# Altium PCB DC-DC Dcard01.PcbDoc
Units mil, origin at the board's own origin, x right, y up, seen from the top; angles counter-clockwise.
Board outline 1550 x 1330 mil, 2 copper layers (Top Layer, Bottom Layer), stack 62 mil thick; 64 components, 26 nets, 145 pads, 30 vias.
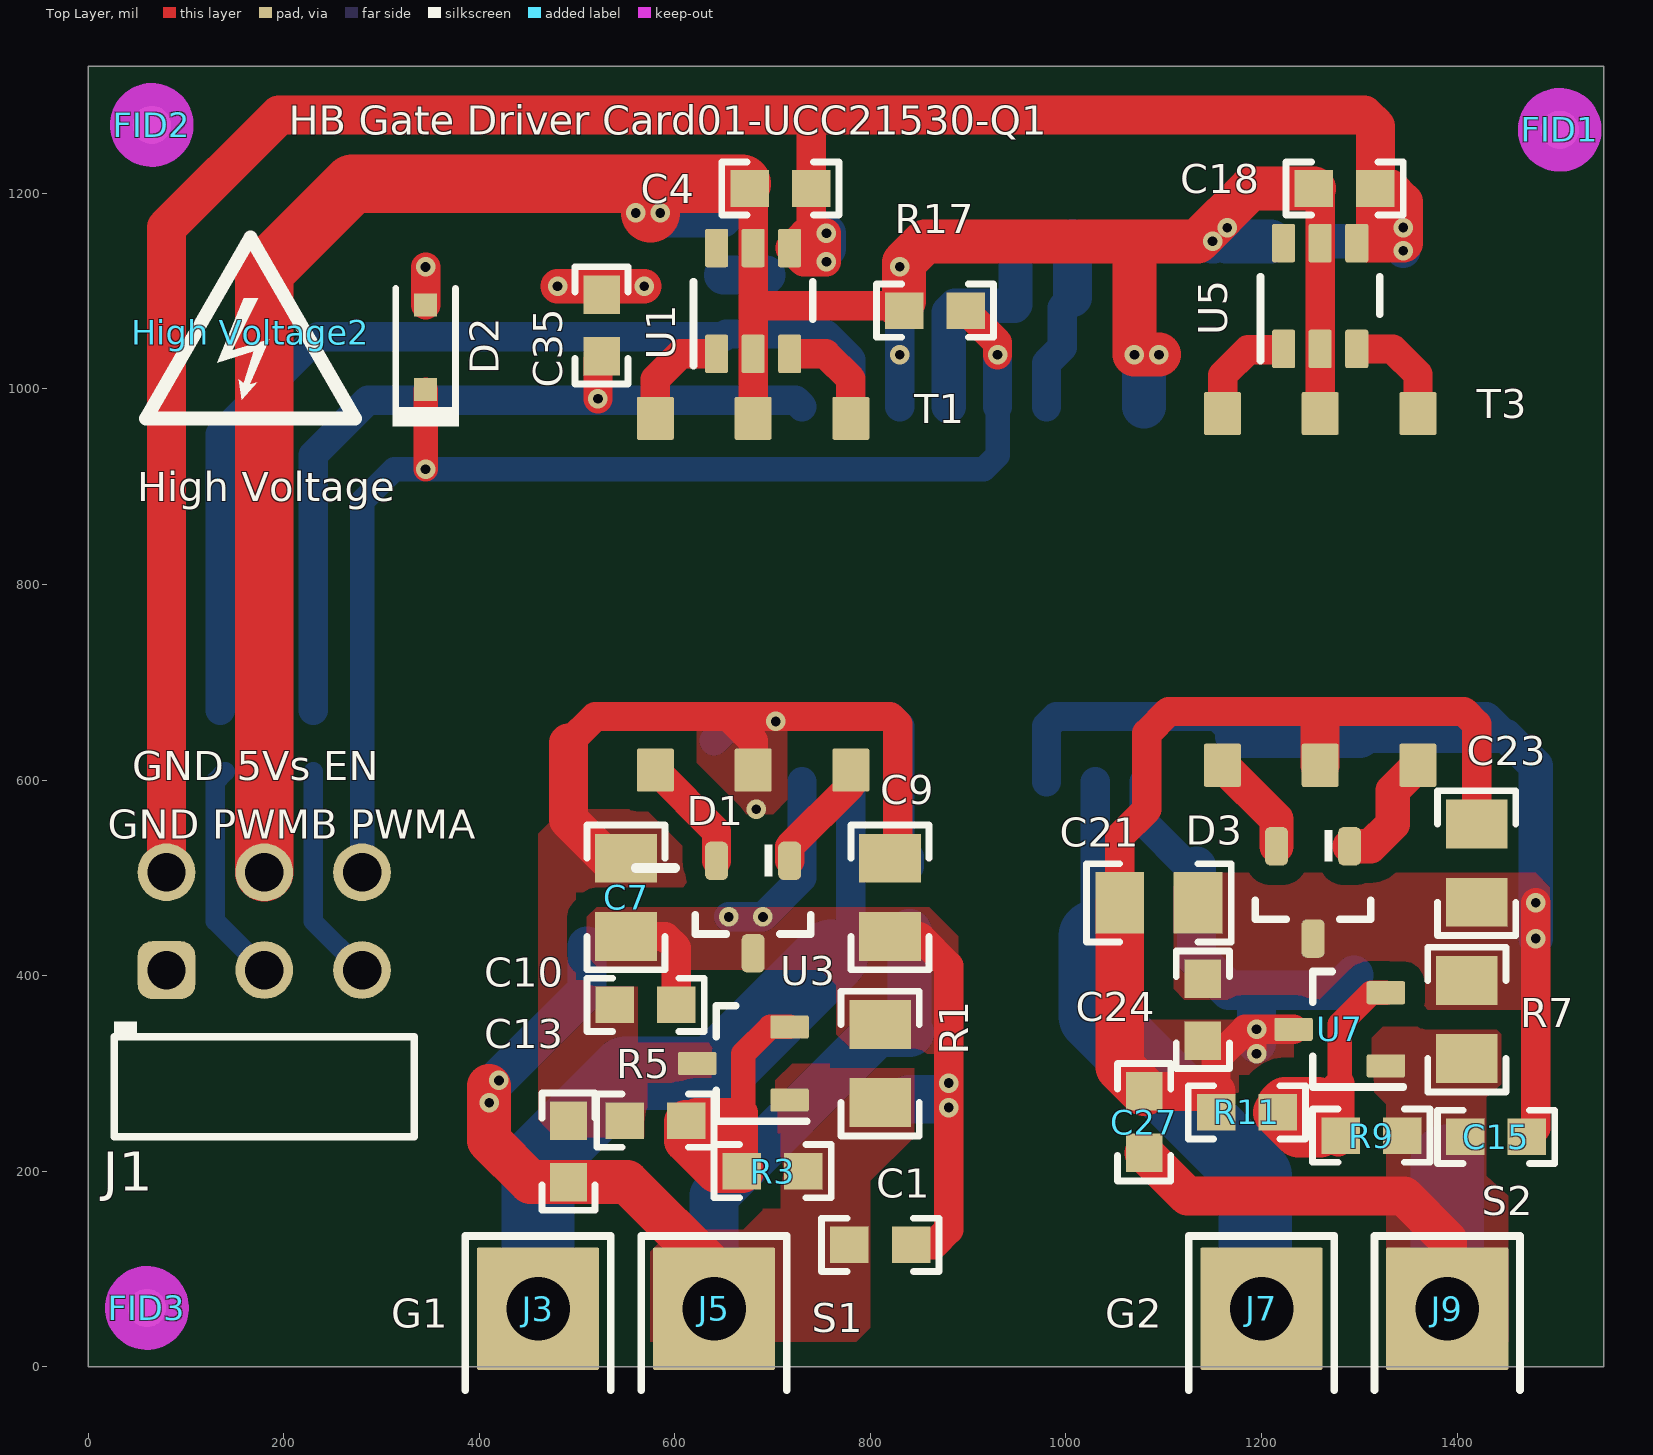
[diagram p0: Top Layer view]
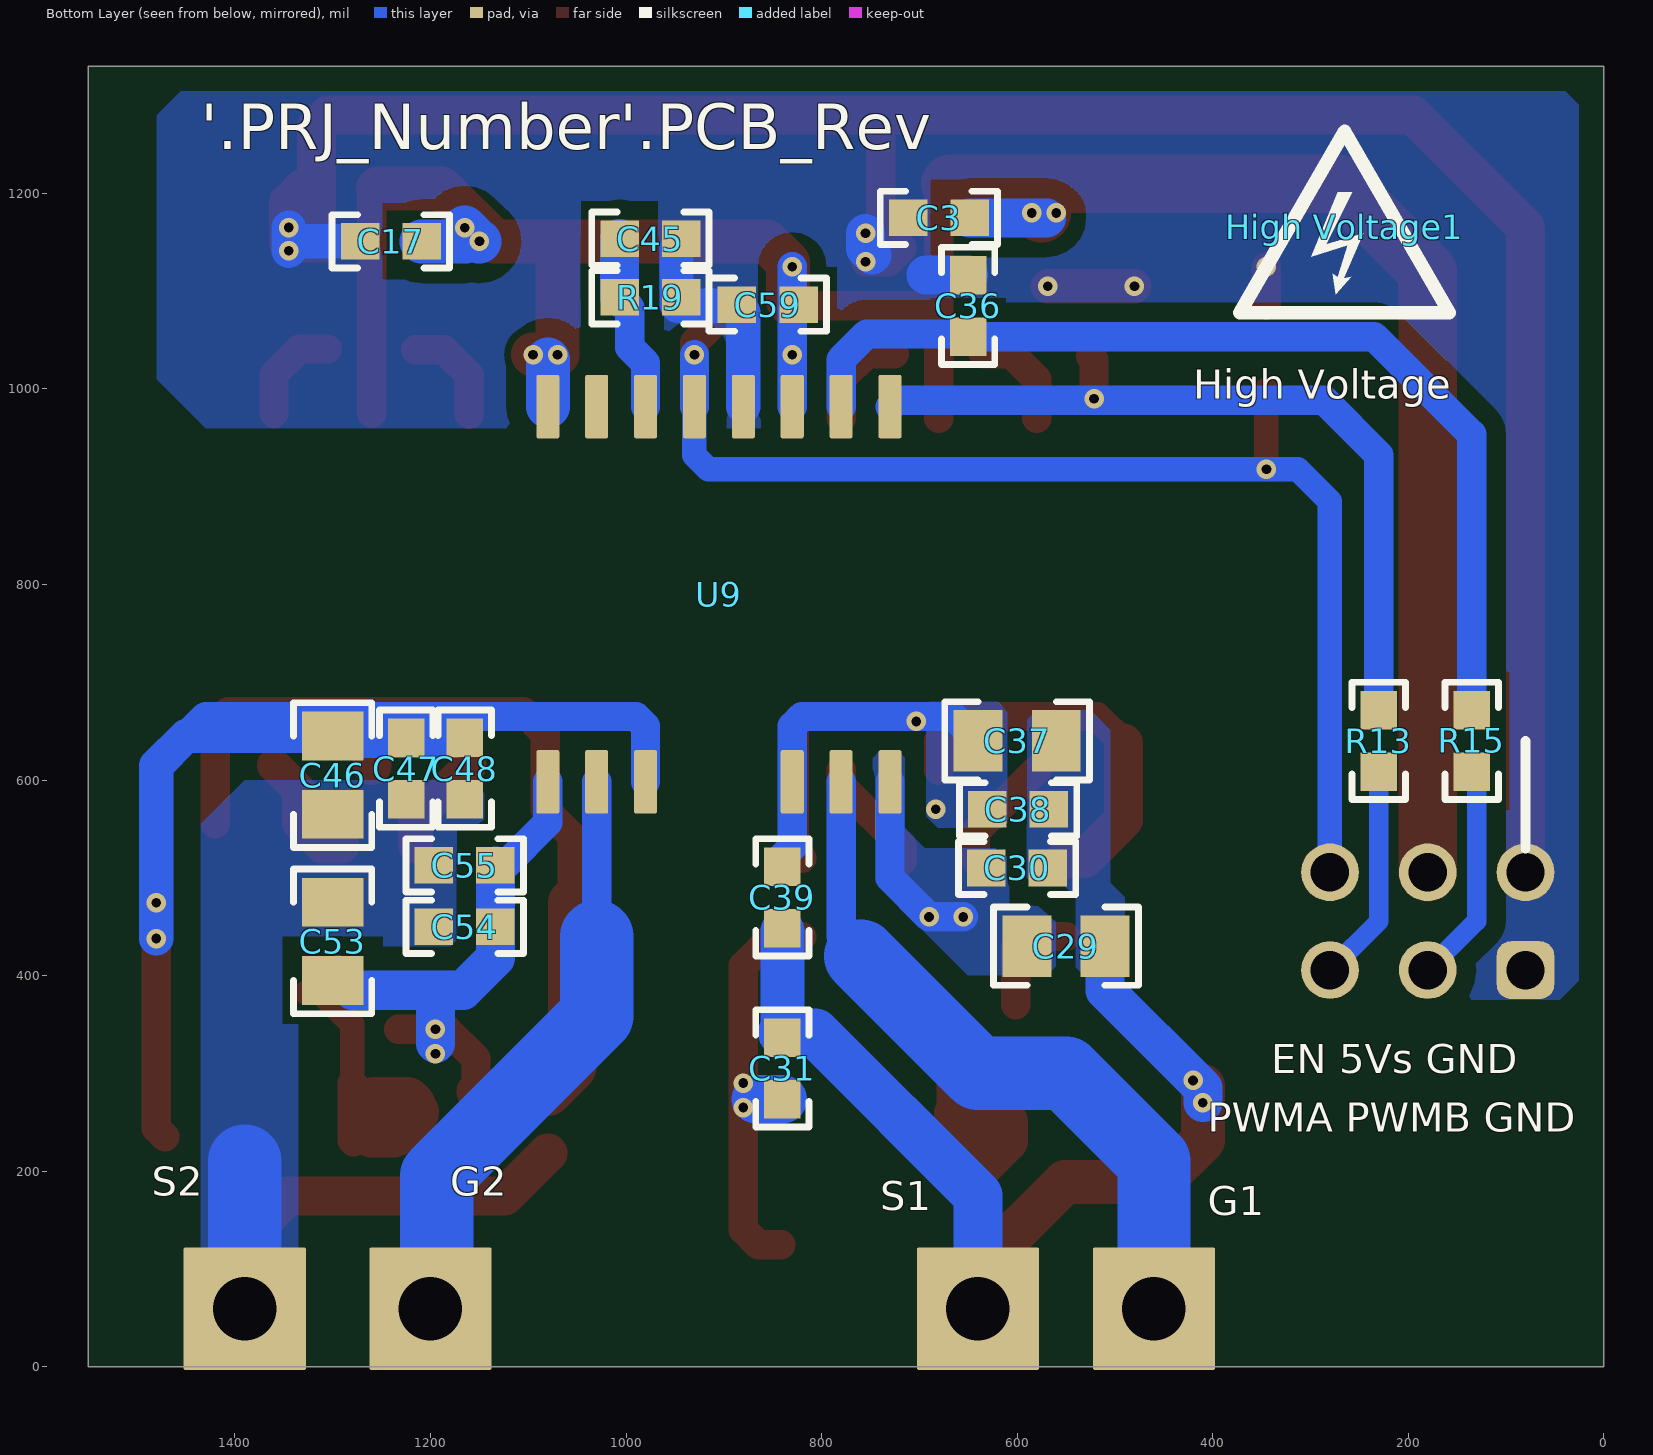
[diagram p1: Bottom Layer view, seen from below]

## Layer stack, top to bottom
Top Solder: solder mask 0.4, Solder Resist, Dk 3.5
Top Layer: signal copper 1.4
Dielectric2: dielectric 59.2, FR-4, Dk 4.8
Bottom Layer: signal copper 1.4
Bottom Solder: solder mask 0.4, Solder Resist, Dk 3.5

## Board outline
0,0 1550,0 1550,1330 0,1330

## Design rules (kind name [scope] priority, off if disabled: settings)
AcuteAngle [All] p1: minimum=4.50000000000000E+0001 checktracksonly=FALSE
AssemblyTestPointUsage [All] p1: valid=2
BoardOutlineClearance BoardOutlineClearance_MountingHoles [OnCopper and InComponentClass('Mounting Holes')] p1: gap=40 ignorepadtopadclearanceinfootprint=FALSE
BoardOutlineClearance BoardOutlineClearance_Poly [OnCopper and IsPoly] p2: gap=25 ignorepadtopadclearanceinfootprint=FALSE
BoardOutlineClearance [OnCopper and Not InComponentClass('Logo') and not InComponentClass('FiducialMark') and not InRegion(1000,500,4000,800) and not InPoly] p3: gap=0 ignorepadtopadclearanceinfootprint=FALSE
Clearance Clearance_Keepouts [((IsTrack Or IsArc) And Not InPoly) And IsFree and IsKeepOut vs ((IsTrack Or IsArc) And Not InPoly) And IsFree and IsKeepOut] p1: gap=0 ignorepadtopadclearanceinfootprint=FALSE
Clearance Clearance_Poly [InPolygon] p2: gap=20 ignorepadtopadclearanceinfootprint=FALSE
Clearance Clearance_FiducialMark [IsKeepOut and InComponentClass('FiducialMark') vs IsPad and InComponentClass('FiducialMark')] p3: gap=0 ignorepadtopadclearanceinfootprint=FALSE
Clearance [All] p4: gap=7.87 ignorepadtopadclearanceinfootprint=FALSE except(0: Arc-Hole Track-Hole SMDPad-Hole THPad-Hole Via-Hole Fill-Hole Poly-Hole Region-Hole Text-Hole)
ComponentClearance ComponentClearance_MountingHoles_FiducialMarks [InComponentClass('Mounting Holes') vs InComponentClass('FiducialMark')] p1: gap=50 collisioncheckmode=3 verticalgap=10 showdistances=FALSE
ComponentClearance ComponentClearance_Shunt [InComponentClass('Header') vs InComponentClass('Shunt')] p2: gap=0 collisioncheckmode=3 verticalgap=0 showdistances=FALSE
ComponentClearance ComponentClearance_Logo [InComponentClass('Logo')] p3: gap=50 collisioncheckmode=3 verticalgap=10 showdistances=FALSE
ComponentClearance ComponentClearance_ScrewToNut [(HasFootprint('NY PMS 440 0025 PH')) vs (HasFootprint('Keystone_1902C'))] p4: gap=5 collisioncheckmode=3 verticalgap=10 showdistances=FALSE
ComponentClearance ComponentClearance_MountingHoles [InComponentClass('Mounting Holes')] p5: gap=250 collisioncheckmode=3 verticalgap=100000 showdistances=FALSE
ComponentClearance ComponentClearance_SmallPassives [HasFootprint('0201*') or HasFootprint('0402*') or HasFootprint('0508') or HasFootprint('0603*') or HasFootprint('0612') or HasFootprint('0805*') or HasFootprint('0815*') or HasFootprint('0830*') or HasFootprint('1206*') or HasFootprint('1210*') or HasFootprint('1808*') or HasFootprint('1812*') or HasFootprint('1825*') or HasFootprint('2010*') or HasFootprint('2220*') or HasFootprint('2225*') or HasFootprint('2512*') or HasFootprint('2728*') or HasFootprint('3518*') vs HasFootprint('0201*') or HasFootprint('0402*') or HasFootprint('0508') or HasFootprint('0603*') or HasFootprint('0612') or HasFootprint('0805*') or HasFootprint('0815*') or HasFootprint('0830*') or HasFootprint('1206*') or HasFootprint('1210*') or HasFootprint('1808*') or HasFootprint('1812*') or HasFootprint('1825*') or HasFootprint('2010*') or HasFootprint('2220*') or HasFootprint('2225*') or HasFootprint('2512*') or HasFootprint('2728*') or HasFootprint('3518*')] p6: gap=14.96 collisioncheckmode=3 verticalgap=10 showdistances=FALSE
ComponentClearance ComponentClearance_THtoSMT [IsThruComponent vs IsSMTComponent] p7: gap=40 collisioncheckmode=3 verticalgap=30 showdistances=FALSE
ComponentClearance ComponentClearance_THtoTH [IsThruComponent vs IsThruComponent] p8: gap=30 collisioncheckmode=3 verticalgap=30 showdistances=FALSE
ComponentClearance [All] p9: gap=30 collisioncheckmode=3 verticalgap=10 showdistances=FALSE
DiffPairsRouting [All] p1: maxlimit=100 minlimit=10 mostfreqgap=10 toplayer_minwidth=15 toplayer_maxwidth=15 toplayer_prefwidth=15 bottomlayer_minwidth=15 bottomlayer_maxwidth=15 bottomlayer_prefwidth=15 maxuncoupledlength=1000
FabricationTestPointUsage TestPointUsage [All] p1: valid=2 allowmultiple=FALSE
FabricationTestpoint Testpoint [All] p1: side=3 testpointundercomponent=TRUE minsize=40 maxsize=100 preferedsize=60 minholesize=0 maxholesize=40 preferedholesize=32 testpointgrid=1 allowsidetop=TRUE allowsidebottom=TRUE usegrid=TRUE gridtolerance=0.01
FanoutControl Fanout_LCC [IsLCC] p1: bgadir=Out bgaviamode=Centered fanoutstyle=Auto fanoutdirection=Alternating viagrid=1 // Fanout_LCC (Default Rule)
FanoutControl Fanout_BGA [IsBGA] p2: bgadir=Out bgaviamode=Centered fanoutstyle=Auto fanoutdirection=Alternating viagrid=1 // Fanout_BGA (Default Rule)
FanoutControl Fanout_Default [All] p4: bgadir=Out bgaviamode=Centered fanoutstyle=Auto fanoutdirection=Alternating viagrid=1 // Fanout_Default (Default Rule)
FanoutControl Fanout_Small [(CompPinCount < 5)] p5: bgadir=Out bgaviamode=Centered fanoutstyle=Auto fanoutdirection=OutThenIn viagrid=1 // Fanout_Small (Default Rule)
HoleSize [All] p1: absolutevalues=TRUE maxlimit=251 minlimit=7.87 maxpercent=80.000 minpercent=20.000
MinimumAnnularRing MinimumAnnularRing_ThermalPadVias [IsVia and InAnyComponent] p1: minimumring=5.91
MinimumAnnularRing [All] p2: minimumring=4
MinimumSolderMaskSliver MinimumSolderMaskSliver_Logo [InComponentClass('Logo') vs InComponentClass('Logo')] p1: minsoldermaskwidth=0.7
MinimumSolderMaskSliver [All] p2: minsoldermaskwidth=0.9
PlaneConnect [All] p1: planeconnectstyle=Relief reliefexpansion=10 reliefentries=4 reliefconductorwidth=10 reliefairgap=10
PolygonConnect [All] p1: connectstyle=Direct reliefconductorwidth=10 reliefentries=4 polygonreliefangle="90 Angle" airgapwidth=10
RoutingVias ThermalPadVias [IsVia and InAnyComponent] p1: holewidth=7.87 width=19.68 viastyle="Through Hole" minholewidth=7.87 minwidth=19.68 maxholewidth=12.99 maxwidth=23.62
RoutingVias [All] p2: holewidth=16 width=34 viastyle="Through Hole" minholewidth=4 minwidth=18 maxholewidth=40 maxwidth=65
SilkToBoardRegionClearance [Not ((IsComment or IsDesignator) And (Hide <> 'False')) and not InRegion(1000,500,4000,800)] p1:
SilkToSilkClearance SilkToSilkClearance_Pb-FreeLogo [(HasFootprint('Pb-Free_Overlay_Medium') OR HasFootprint('Pb-Free_Overlay_Small')) vs (HasFootprint('Pb-Free_Overlay_Medium') OR HasFootprint('Pb-Free_Overlay_Small'))] p1: silktosilkclearance=0
SilkToSilkClearance [All] p2: silktosilkclearance=4
SilkToSolderMaskClearance SilkToComponentPadClearance [(IsPad or IsFill or IsRegion) and InAnycomponent] p1: minsilkscreentomaskgap=0 clearancetoexposedcopper=TRUE
SilkToSolderMaskClearance "Silk to Solder Mask Opening" [All] p2: minsilkscreentomaskgap=0 clearancetoexposedcopper=FALSE
SolderMaskExpansion [All] p1: expansion=1.97
Width [All] p1: maxlimit=150 minlimit=6 preferedwidth=10 checkconnectedcopper=TRUE
15 further rules are at their usual default settings.

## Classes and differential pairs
component class "TIDM-02009_Gate Drive1": C1 C3 C4 C7 C9 C10 C13 C15 C17 C18 C21 C23 C24 C27 C29 C30 C31 C35 C36 C37 C38 C39 C45 C46 C47 C48 C53 C54 C55 C59 D1 D2 D3 J1 J3 J5 J7 J9 R1 R3 R5 R7 R9 R11 R13 R15 R17 R19 T1 T3 U1 U3 U5 U7 U9
component class Header: J1
component class TIDM-02009_DC_Hardware: FID1 FID2 FID3 "High Voltage1" "High Voltage2" ZZ1 ZZ2 ZZ3 ZZ4
component class FiducialMark: FID1 FID2 FID3
component class AssemblyNote: ZZ1 ZZ2 ZZ3 ZZ4

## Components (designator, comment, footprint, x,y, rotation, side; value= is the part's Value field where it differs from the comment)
C1 "CGA3E2X7R1E104K080AA" 0603 810,124.5 r180 top value=0.1uF
C3 "GRT188C81A106ME13D" 0603 680,1175 r0 bottom value=10uF
C4 "CGA3E2X7R1E104K080AA" 0603 707.91,1205 r0 top value=0.1uF
C7 "GRT21BR61H475KE13L" 0805_HV 550,480 r90 top value=4.7uF
C9 "GRT21BR61H475KE13L" 0805_HV 820,480 r90 top value=4.7uF
C10 "CGA3E2X7R1E104K080AA" 0603 570,370 r180 top value=0.1uF
C13 "CGA3E2X7R1E104K080AA" 0603 491.16,220 r90 top value=0.1uF
C15 "CGA3E2X7R1E104K080AA" 0603 1440,235 r180 top value=0.1uF
C17 "GRT188C81A106ME13D" 0603 1240.57,1150.98 r0 bottom value=10uF
C18 "CGA3E2X7R1E104K080AA" 0603 1285,1205 r0 top value=0.1uF
C21 "GRT21BR61H475KE13L" 0805_HV 1095,474.42 r180 top value=4.7uF
C23 "GRT21BR61H475KE13L" 0805_HV 1420,515 r90 top value=4.7uF
C24 "CGA3E2X7R1E104K080AA" 0603 1140,365 r270 top value=0.1uF
C27 "CGA3E2X7R1E104K080AA" 0603 1080,250 r90 top value=0.1uF
C29 "GRT21BR61H475KE13L" 0805_HV 550,430 r180 bottom value=4.7uF
C30 "CGA3E2X7R1E104K080AA" 0603 600,510 r180 bottom value=0.1uF
C31 "CGA3E2C0G1H103J080AA" 0603 840,305 r90 bottom value=0.01uF
C35 "GCM1885C2A101JA16D" 0603 525,1065 r90 top value=100pF
C36 "GCM1885C2A101JA16D" 0603 650,1085 r90 bottom value=100pF
C37 "GRT21BR61H475KE13L" 0805_HV 600,640 r0 bottom value=4.7uF
C38 "CGA3E2X7R1E104K080AA" 0603 598.98,570 r0 bottom value=0.1uF
C39 "CGA3E2C0G1H103J080AA" 0603 840,480 r90 bottom value=0.01uF
C45 "GRM188R71C222KA01D" 0603 975,1153.62 r180 bottom value=2200pF
C46 "GRT21BR61H475KE13L" 0805_HV 1300,605 r270 bottom value=4.7uF
C47 "CGA3E2X7R1E104K080AA" 0603 1225,611.69 r270 bottom value=0.1uF
C48 "CGA3E2C0G1H103J080AA" 0603 1165,611.69 r270 bottom value=0.01uF
C53 "GRT21BR61H475KE13L" 0805_HV 1300,435 r270 bottom value=4.7uF
C54 "CGA3E2X7R1E104K080AA" 0603 1165,449.69 r180 bottom value=0.1uF
C55 "CGA3E2C0G1H103J080AA" 0603 1165,512.68 r180 bottom value=0.01uF
C59 "CGA3E2X7R1E104K080AA" 0603 855,1086.3 r0 bottom value=0.1uF
D1 "BAV70-E3-08" SOT-23 680,470 r270 top value=70V
D2 "SZMM3Z3V3ST1G" SOD-323 345,1042.56 r90 top value=3.3V
D3 "BAV70-E3-08" SOT-23 1252.72,485 r270 top value=70V
FID1 "Fiducial" Fiducial10-20 1505,1265 r0 top
FID2 "Fiducial" Fiducial10-20 65,1270 r0 top
FID3 "Fiducial" Fiducial10-20 60,60 r0 top
"High Voltage1" "DANGER HIGH VOLTAGE" IEC_HighVoltage_Small 265,1165.97 r180 bottom
"High Voltage2" "DANGER HIGH VOLTAGE" IEC_HighVoltage_Small 166,1057.76 r0 top
J1 "90122-0763" Molex_90122-0763 180,455.59 r90 top
J3 "3620-2-32-15-00-00-08-0" Mill-Max_3620-2-32-xx-00-00-08-0 460,-40 r0 top
J5 "3620-2-32-15-00-00-08-0" Mill-Max_3620-2-32-xx-00-00-08-0 640,-40 r0 top
J7 "3620-2-32-15-00-00-08-0" Mill-Max_3620-2-32-xx-00-00-08-0 1200,-40 r0 top
J9 "3620-2-32-15-00-00-08-0" Mill-Max_3620-2-32-xx-00-00-08-0 1390,-40 r0 top
R1 "ERJ-P06F4701V" 0805_HV 810,310 r90 top value=4.70k
R3 "RT0603DRE073K01L" 0603 700,200 r0 top value=3.01k
R5 "RT0603DRE074K99L" 0603 580,251.5 r0 top value=4.99k
R7 "ERJ-P06F4701V" 0805_HV 1410,355 r90 top value=4.70k
R9 "RT0603DRE073K01L" 0603 1312.28,236.3 r0 top value=3.01k
R11 "RT0603DRE074K99L" 0603 1185,260 r0 top value=4.99k
R13 "CRCW06030000Z0EA" 0603 230.1,640 r270 bottom value=0
R15 "CRCW06030000Z0EA" 0603 135,640 r270 bottom value=0
R17 "RC0603JR-075K1L" 0603 866.02,1080 r0 top value=5.1k
R19 "CRCW06033K09FKEA" 0603 975,1093.62 r0 bottom value=3.09k
T1 "750317722" Wurth_750317722 680,790 r270 top
T3 "750317722" Wurth_750317722 1260,795 r270 top
U1 "SN6505DQDBVRQ1" DBV0006A_N 680,1090 r90 top
U3 "TL431AQDBZRQ1" DBZ0003A_N 670,310 r180 top
U5 "SN6505DQDBVRQ1" DBV0006A_N 1260,1095 r90 top
U7 "TL431AQDBZRQ1" DBZ0003A_N 1280,345 r180 top
U9 "UCC21530QDWKRQ1" DWK0014A 905,790 r270 bottom
ZZ1 "This Assembly Note is for PCB labels only" AssemblyNoteLabel 185,3938 r0 top
ZZ2 "These assemblies are ESD sensitive, ESD precautions shall be observed." AssemblyNote 185,3829.11 r0 top
ZZ3 "These assemblies must be clean and free from flux and all contaminants. Use of no clean flux is not acceptable." AssemblyNote 185,3740.56 r0 top
ZZ4 "These assemblies must comply with workmanship standards IPC-A-610 Class 2, unless otherwise specified." AssemblyNote 185,3652 r0 top

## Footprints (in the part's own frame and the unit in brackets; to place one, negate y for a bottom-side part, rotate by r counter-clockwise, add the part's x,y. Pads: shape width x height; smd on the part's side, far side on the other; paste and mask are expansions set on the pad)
0603 [mm] "0603 from SM-752 data"
  rect 1x0.95 smd: 1(-0.8,0) 2(0.8,0)
  silkscreen extent -1.52,-0.69 1.52,0.69, body extent -0.87,-0.47 0.87,0.47, height 1
0805_HV [mil] "0805 with 30mil clearance between pads"
  rect 50x63 smd: 1(-40,0) 2(40,0)
  silkscreen extent -74,-40 74,40, body extent -43,-29 43,29, height 57
AssemblyNote [mil] "Assembly Note"
AssemblyNoteLabel [mil] "Assembly Note for PCB Labels"
DBV0006A_N [mm] "SOT23, 6-Leads, Body 2.9x1.6mm, Pitch 0.95mm, Lead Span 2.8mm, IPC Medium Density"
  rrect17% 1x0.6 smd: 1(-1.375,0.95) 2(-1.375,0) 3(-1.375,-0.95) 4(1.375,-0.95) 5(1.375,0) 6(1.375,0.95)
  silkscreen extent -1.68,-1.55 0.5,1.55, body extent -1.42,-1.46 1.42,1.46, height 1.12
DBZ0003A_N [mm] "SOT23, 3-Leads, Body 2.9x1.3mm, Pitch 0.95mm, Lead Span 2.4mm, IPC Medium Density"
  rrect17% 1x0.6 smd: 1(-1.2,0.95) 2(-1.2,-0.95) 3(1.2,0)
  silkscreen extent -1.65,-1.5 0.7,1.5, body extent -1.26,-1.46 1.26,1.46, height 0.98
DWK0014A [mm] "SOIC-14"
  rrect17% 1.65x0.6 smd: 1(-4.875,4.445) 2(-4.875,3.175) 3(-4.875,1.905) 4(-4.875,0.635) 5(-4.875,-0.635) 6(-4.875,-1.905) 7(-4.875,-3.175) 8(-4.875,-4.445) 9(4.875,-4.445) 10(4.875,-3.175) 11(4.875,-1.905) 14(4.875,1.905) 15(4.875,3.175) 16(4.875,4.445)
  body extent -5.17,-5.15 5.17,5.15, height 2.59
Fiducial10-20 [mm]
  round 1 smd mask+0.5: 1(0,0)
  Top Layer keep-out circle w1.178: c0,0 r0.5
IEC_HighVoltage_Small [mil]
  silkscreen extent -107,-88 107,97
Mill-Max_3620-2-32-xx-00-00-08-0 [mm] "PCB Pin, 0.04\" DIA, R/A, Edge-Mount"
  rrect3% 3.18x3.18 hole 1.65: 1(0,2.52)
  silkscreen extent -1.89,0.41 1.89,4.41, body extent -1.59,-5.06 1.59,4.11, height 0.65
Molex_90122-0763 [mm] "Header, 2.54mm, 3x2, R/A, TH"
  rrect50% 1.5x1.5 hole 1: 1(-1.27,2.54)
  round 1.5 hole 1: 2(1.27,2.54) 3(-1.27,0) 4(1.27,0) 5(-1.27,-2.54) 6(1.27,-2.54)
  silkscreen extent -5.6,-3.9 -2.6,3.9, body extent -12.27,-3.81 1.57,3.81, height 6.35
SOD-323 [mm] "NXP recommended land pattern"
  rect 0.6x0.6 smd paste-0.05: 1(-1.1,0) 2(1.1,0)
  silkscreen extent -2.06,-0.86 1.53,0.86, body extent -1.3,-0.67 1.3,0.68, height 1.1
SOT-23 [mm] "SOT23, 3-Leads, Body 2.9x1.3mm, Pitch 0.95mm, Lead Span 2.5mm, IPC Medium Density"
  rrect50% 1x0.6 smd: 1(-1.2,0.95) 2(-1.2,-0.95) 3(1.2,0)
  silkscreen extent -1.63,-1.5 0.7,1.5, body extent -1.16,-1.45 1.21,1.45, height 1
Wurth_750317722 [mm] "SMD, 6-Leads, Body 7.14x6.73mm, Pitch 2.54mm"
  rrect10% 1.12x0.96 smd: 1(-4.57,2.54) 2(-4.57,0) 3(-4.57,-2.54) 4(4.57,-2.54) 5(4.57,0) 6(4.57,2.54)
  body extent -5.23,-3.36 5.23,3.37, height 4.19

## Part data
C1 C4 C10 C13 C15 C18 C24 C27 C30 C38 C47 C54 C59: "CAP, CERM, 0.1 µF, 25 V,+/- 10%, X7R, AEC-Q200 Grade 1, 0603", Cap_Case=0603, Manufacturer=TDK, Supplier Part Number 1=445-5667-1-ND, TempCo=X7R, Tolerance_%=10, Value2=25V, ValueDisplayed=0.1µF
C3 C17: "CAP, CERM, 10 µF, 10 V,+/- 20%, X6S, AEC-Q200 Grade 2, 0603", Cap_Case=0603, Manufacturer=MuRata, Supplier Part Number 1=490-12283-1-ND, TempCo=X6S, Tolerance_%=20, Value2=10V, ValueDisplayed=10µF
C7 C9 C21 C23 C29 C37 C46 C53: "CAP, CERM, 4.7 µF, 50 V,+/- 10%, X5R, AEC-Q200 Grade 3, 0805", Cap_Case=0805, Manufacturer=MuRata, Supplier Part Number 1=490-12394-1-ND, TempCo=X5R, Tolerance_%=10, Value2=50V, ValueDisplayed=4.7µF
C31 C39 C48 C55: "CAP, CERM, 0.01 µF, 50 V,+/- 5%, C0G/NP0, AEC-Q200 Grade 1, 0603", Cap_Case=0603, Manufacturer=TDK, Supplier Part Number 1=445-6916-1-ND, TempCo=C0G/NP0, Tolerance_%=5, Value2=50V, ValueDisplayed=0.01µF
C35 C36: "CAP, CERM, 100 pF, 100 V,+/- 5%, C0G/NP0, AEC-Q200 Grade 1, 0603", Cap_Case=0603, Manufacturer=MuRata, Supplier Part Number 1=490-4771-1-ND, TempCo=C0G/NP0, Tolerance_%=5, Value2=100V, ValueDisplayed=100pF
C45: "CAP, CERM, 2200 pF, 16 V,+/- 10%, X7R, 0603", Cap_Case=0603, Manufacturer=MuRata, Supplier Part Number 1=GRM188R71C222KA01D-ND, TempCo=X7R, Tolerance_%=10, Value2=16V, ValueDisplayed=2200pF
D1 D3: "Diode, Switching, 70 V, 0.25 A, AEC-Q101, SOT-23", Manufacturer=Vishay-Semiconductor, Supplier Part Number 1=BAV70-E3-08CT-ND, Value1=0.25A, Value2=1.25V
D2: library part CMP-0085730-1, "Diode, Zener, 3.3 V, 300 mW, AEC-Q101, SOD-323", Manufacturer="ON Semiconductor", Power_W=300mW, Value1=0.3W
FID1 FID2 FID3: library part CMP-0077181-1, "Fiducial mark.  There is nothing to buy or mount.", Manufacturer=N/A
"High Voltage1" "High Voltage2": library part CMP-0074835-1, "IEC 61010-1 High Voltage Warning"
J1: library part CMP-0077741-1, "Header, 2.54mm, 3x2, Gold, R/A, TH", Color=Black, Current_A=3A, Manufacturer=Harwin, PartNumber=M20-9950345, Voltage_V=350V
J3 J5 J7 J9: library part CMP-0055044-1, Manufacturer=Mill-Max, Supplier Part Number 1=ED1278-ND
R1 R7: library part CMP-0021852-2, "RES, 4.70 k, 1%, 0.5 W, AEC-Q200 Grade 0, 0805", Manufacturer=Panasonic, Power_W=500mW, Supplier Part Number 1=P16073CT-ND, TempCo="100 ppm/C", Tolerance_%=1%, Value2=0.5W, Value_Code=4k70, ValueDisplayed=4.70k
R3 R9: "RES, 3.01 k, 0.5%, 0.1 W, 0603", Manufacturer="Yageo America", Power_W=0.1, TempCo="50 ppm/C", Tolerance_%=0.5, Value1=0.5%, Value2=0.1W, Value_Code=3k01, ValueDisplayed=3.01k
R5 R11: "RES, 4.99 k, 0.5%, 0.1 W, 0603", Manufacturer="Yageo America", Power_W=0.1, TempCo="50 ppm/C", Tolerance_%=0.5, Value1=0.5%, Value2=0.1W, Value_Code=4k99, ValueDisplayed=4.99k
R13 R15: "RES, 0, 5%, 0.1 W, 0603", Manufacturer=Vishay-Dale, Power_W=0.1, Supplier Part Number 1=541-0.0GCT-ND, TempCo="200 ppm/C", Tolerance_%=5, Value1=5%, Value2=0.1W, Value_Code=0000, ValueDisplayed=0
R17: "RES, 5.1 k, 5%, 0.1 W, 0603", Manufacturer="Yageo America", Power_W=0.1, Supplier Part Number 1=311-5.1KGRCT-ND, TempCo="100 ppm/C", Tolerance_%=5, Value1=5%, Value2=0.1W, Value_Code=5k10, ValueDisplayed=5.1k
R19: "RES, 3.09 k, 1%, 0.1 W, 0603", Manufacturer=Vishay-Dale, Power_W=0.1, Supplier Part Number 1=541-3.09KHCT-ND, TempCo="100 ppm/C", Tolerance_%=1, Value1=1%, Value2=0.1W, Value_Code=3k09, ValueDisplayed=3.09k
T1 T3: library part CMP-0081994-1, "Transformer, 320 uH, SMD", Manufacturer="Wurth Elektronik"
U1 U5: library part CMP-0860735-1, "SN6505DQDBVRQ1, DBV0006A (SOT-23-6)", Alternate Manufacturer="Texas Instruments", Alternate PartNumber=SN6505DQDBVTQ1
U3 U7: "Automotive Catalog Adjustable Precision Shunt Regulator, 34 ppm / degC, 100 mA, -40 to 125 degC, 3-pin SOT-23 (DBZ), Green (RoHS & no Sb/Br)", Alternate Manufacturer="Texas Instruments", Alternate PartNumber=Equivalent, Rating=Automotive, Supplier Part Number 1=296-21853-2-ND, Temp Coeff(Typ)(ppm/ degree C)=34
U9: library part CMP-0083997-1, "4-A, 6-A, 5.7-kVRMS Isolated Dual-Channel Gate Driver with Enable, DWK0014A (SOIC-14)", Alternate Manufacturer="Texas Instruments", Alternate PartNumber=UCC21530QDWKQ1
ZZ1: library part CMP-0003616-3
ZZ2: library part CMP-0077236-1
ZZ3: library part CMP-0077237-1
ZZ4: library part CMP-0077238-1

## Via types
v1: diameter 20, hole 10, Top Layer to Bottom Layer, 30 vias

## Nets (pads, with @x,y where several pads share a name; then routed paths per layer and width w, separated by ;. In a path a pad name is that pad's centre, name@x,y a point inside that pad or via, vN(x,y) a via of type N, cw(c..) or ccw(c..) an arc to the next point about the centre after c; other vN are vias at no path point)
5Vs: C3.1 C4.1 C17.1 C18.1 C59.1 J1.4 R17.1 T1.2 T3.2 U1.2 U1.5 U5.2 U5.5 U9.3 U9.8 | length 2785.7
  Top Layer w30: C4.1 680,1201.42 U1.5 680,1085 ; T1.2 U1.2 680,1085 ; R17.1@829.53,1085 680,1085 ; C18.1@1256.42,1210 1260,1206.42 U5.5 U5.2 T3.2
  Top Layer w45: R17.1@829.53,1085 834.53,1090 834.53,1129.53 855.98,1150.98 1080,1150.98 ; v1(1095,1035) v1(1070,1035) 1070,1140.98 1080,1150.98 ; C18.1 1188.7,1205 1134.68,1150.98 1080,1150.98
  Top Layer w60: J1.4 180,1120 270,1210 590,1210 ; v1@575,1180 575,1195 590,1210 ; C4.1@668.5,1210 590,1210
  Bottom Layer w30: C59.1@823.5,1085 C59.1@830,1078.5 ; U9.3 v1(830,1035) C59.1@830,1078.5 ; v1(830,1125) C59.1@830,1078.5
  Bottom Layer w40: 570,1175 C3.1
  Bottom Layer w45: U9.8 1080,1030 ; v1(1150,1150.98) 1151.06,1150.98 v1(1165,1164.92) ; 1164.02,1150.98 C17.1
  other v1: 560,1180 585,1180
+15V_1: C1.1 C7.1 C9.1 C10.1 C29.1 C30.1 C31.1 D1.3 R1.2 U9.16 | length 718.8
  Top Layer w30: C7.1 590,440 601.5,428.5 C10.1 ; C9.1 850,440 880,410 880,340 880,315 880,140 864.5,124.5 C1.1
  Bottom Layer w30: v1(655,460) v1(690,460) 730,500 U9.16
  Bottom Layer w50: C31.1 867.05,273.5
  other v1: 880,265 880,290
+15V_2: C15.1 C21.1 C23.1 C24.1 C46.1 C47.1 C48.1 D3.3 R7.2 U9.11 | length 1305.8
  Top Layer w30: C15.1 1480.39,243.9 v1(1480.39,437.76) v1(1480.39,474.42)
  Bottom Layer w30: U9.11 980,655 990,665 1154.81,665 ; C48.1@1174.81,645 1154.81,665 ; 1450,645 1430,665 1154.81,665
  Bottom Layer w35: C46.1 1450,645 1480.39,614.61 v1(1480.39,474.42) v1(1480.39,437.76)
  Bottom Layer w45: C48.1@1174.81,645 C46.1
-4V_1: C7.2 C9.2 C10.2 C13.2 C37.2 C38.2 C39.2 R5.1 T1.5 U3.3 U9.14 | length 1062.6
  Top Layer w30: 491.16,637.66 518.5,665 655,665 ; T1.5 680,640 655,665 ; C9.2 828,528 828,657 820,665 655,665
  Top Layer w40: 491.16,637.66 491.16,559.42 530.58,520 C7.2
  Bottom Layer w30: C37.2 665,665 820,665 830,655 U9.14 830,531.5 840,521.5 C39.2
  other v1: 683.16,570 703.05,659.91
-4V_2: C21.2 C23.2 C24.2 C27.2 C53.2 C54.2 C55.2 R11.1 T3.5 U7.3 U9.9 | length 1585.5
  Top Layer w20: v1(1195,320) v1(1195,345)
  Top Layer w30: C21.2 1055,542.24 1082.76,570 1082.76,647.76 1105,670 1260,670 ; R11.1 1153.5,281.5 1153.5,315 1183.5,345 v1(1195,345) U7.3 ; 1260,662 1260,670 ; C23.2 1420,657 1407,670 1260,670
  Top Layer w40: C27.2 1153.5,281.5 ; T3.5 1260,662
  Top Layer w50: C21.2 1055,306.5 C27.2
  Bottom Layer w30: U9.9 1080,556.46 1124.37,512.09 C55.2@1133.5,512.09
  Bottom Layer w40: C55.2@1133.5,512.09 C54.2 1133.5,418.15 1166.65,385 1195,385 ; 1195,330.31 v1(1195,345) 1195,385 ; C53.2@1294.72,400.28 1279.45,385 1195,385
AGND: C3.2 C4.2 C17.2 C18.2 C35.2 C36.2 C45.2 C59.2 D2.2 J1.1 J1.2 R19.1 U1.4 U5.4 U9.4 | length 2945.3
  Top Layer w30: D2.2 v1(345,1124.74) ; 739.41,1280 C4.2 739.41,1166.14 732.4,1159.13 ; v1@755,1157.09 v1(755,1130) 731.54,1130 717.87,1143.66 717.87,1144.61 732.4,1159.13 ; v1(755,1159.13) 732.4,1159.13
  Top Layer w35: v1(480,1105) v1(568.63,1105)
  Top Layer w40: J1.2 80,1165 195,1280 739.41,1280 1305,1280 1316.5,1268.5 C18.2 ; 1310,1149.13 1332.28,1149.13 ; C18.2 1316.5,1164.92 1332.28,1149.13 ; C18.2 1331.02,1205 1345,1191.02 v1(1345,1165) 1345,1149.13 1332.28,1149.13
  Bottom Layer w20: J1.1 J1.1@80.41,405.59
  Bottom Layer w35: U9.4 880,1078.5 886.5,1085 947.2,1085 948.5,1086.3 C45.2@948.5,1143.7 ; C17.2 1335.44,1150.98 v1(1345,1141.42) v1(1345,1165)
  Bottom Layer w40: C36.2 692.99,1116.5 ; v1@748.29,1136.83 755,1143.54 v1(755,1159.13)
EN_1: D2.1 J1.6 R17.2 U9.5 | length 1291.5
  Top Layer w25: v1(345,917.95) D2.1
  Top Layer w30: R17.2 930,1047.52 v1(930,1035)
  Bottom Layer w25: J1.6 280,885 312.95,917.95 915.7,917.95 930,932.26 U9.5
  Bottom Layer w30: U9.5 v1(930,1035)
G_1: J3.1 U9.15 | length 734.1
  Bottom Layer w30: 760,420 780,440 U9.15
  Bottom Layer w39.37: J3.1@460,49.21 J3.1
  Bottom Layer w75: J3.1 460,210 550,300 640,300 760,420
G_2: J7.1 U9.10 | length 612.9
  Bottom Layer w30: 1030,440 U9.10
  Bottom Layer w39.37: J7.1@1193.74,59.21 J7.1
  Bottom Layer w75: 1030,440 1030,358.74 1193.74,195 J7.1@1193.74,59.21
NetC35_1: C35.1 R13.1 U9.1 | length 831.8
  Top Layer w30: v1(521.3,990) 521.3,1029.8 C35.1
  Bottom Layer w30: R13.1 230.1,932.42 286.18,988.5 723.43,988.5 U9.1
NetC36_1: C36.1 R15.1 U9.2 | length 1028.4
  Bottom Layer w30: R15.1 135,953.5 235,1053.5 C36.1 652.65,1056.15 753.85,1056.15 780,1030 U9.2
NetC45_1: C45.1 R19.2 U9.6 | length 182.7
  Bottom Layer w30: U9.6 980,1026.46 996.02,1042.48 996.02,1083.15 R19.2
  Bottom Layer w40: R19.2 C45.1
NetD1_1: D1.1 T1.6 | length 118.8
  Top Layer w30: D1.1 717.4,531.88 780,594.48 T1.6
NetD1_2: D1.2 T1.4 | length 118.8
  Top Layer w30: T1.4 642.6,547.48 D1.2
NetD3_1: D3.1 T3.6 | length 124.2
  Top Layer w35: D3.1 1311.38,532.24 1334.13,555 1334.13,589.21 T3.6
NetD3_2: D3.2 T3.4 | length 105.7
  Top Layer w35: T3.4 1215.32,559.76 D3.2
NetR3_1: R3.1 R5.2 U3.2 | length 378.5
  Top Layer w25: 670,260 670,320 697.4,347.4 U3.2
  Top Layer w30: R5.2@611.5,250 621.5,260 670,260 670,201.5 R3.1
  Top Layer w45: 650,227.27 627.27,250 611.5,250 611.5,231.3 642.8,200 R3.1
NetR9_1: R9.1 R11.2 U7.2 | length 314.9
  Top Layer w25: 1258.03,271.1 1280,293.07 ; 1280,290 1280,293.07 ; U7.2 1312.4,382.4 1280,350 1280,293.07
  Top Layer w30: R9.1@1278.5,230 1280,231.5 1280,290
  Top Layer w50: R11.2 R11.2@1219.63,256.87 ; 1258.03,271.1 1223.84,271.1 1219.63,266.89 R11.2@1219.63,256.87 ; 1260,238.7 1237.8,238.7 R11.2@1219.63,256.87
NetT1_1: T1.1 U1.3 | length 105.3
  Top Layer w30: U1.3@725.45,1035.87 754.13,1035.87 780,1010 T1.1
NetT1_3: T1.3 U1.1 | length 105.4
  Top Layer w30: T1.3 580,1010 605.87,1035.87 U1.1@634.63,1035.87
NetT3_1: T3.1 U5.3 | length 105.3
  Top Layer w30: U5.3@1305.45,1040.87 1334.13,1040.87 1360,1015 T3.1
NetT3_3: T3.3 U5.1 | length 105.4
  Top Layer w30: T3.3@1160.37,974.06 1160.37,1014.13 1186.24,1040 U5.1@1215,1040
PWMA_1: J1.5 R13.2 | length 223.6
  Bottom Layer w20: R13.2 230.1,455.49 J1.5
PWMB_1: J1.3 R15.2 | length 232.8
  Bottom Layer w20: R15.2@140,608.5 130,598.5 130,455.59 J1.3 J1.3@174.96,405.59
S_1: C1.2 C13.1 C29.2 C30.2 C31.2 C37.1 C38.1 C39.1 J5.1 R1.1 R3.2 U3.1 | length 1071.1
  Top Layer w35: J5.1 J5.1@640,100
  Top Layer w45: 410,286.85 v1(410,270) 410,231.09 452.19,188.91 551.09,188.91 J5.1@640,100
  Bottom Layer w40: v1(410,270) 410,285 510,385 C29.2
  Bottom Layer w45: C31.2@840,341.5 C39.1@840,445.55
  Bottom Layer w50: J5.1 640,175 806.5,341.5 C31.2@840,341.5
  other v1: 420,292.78
S_2: C15.2 C27.1 C46.2 C47.2 C48.2 C53.1 C54.1 C55.1 J9.1 R7.1 R9.2 U7.1 | length 571
  Top Layer w40: C27.1 1124.11,174.39 1345.61,174.39 1390,130 J9.1
  Bottom Layer w75: J9.1@1390,56.85 J9.1 1390,210.39
pads on no net: FID1.1 FID2.1 FID3.1 U1.6 U5.6 U9.7

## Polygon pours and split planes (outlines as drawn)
S_2 on Top Layer "TOP_LAYER_S_2_P056" (solid, remove dead copper, pour order 56): 1437.6,347.4 1445,340 1445,288.95 1430,275.53 1430,195 1452.6,175 1452.6,7.6 1445,0 1345,0 1327.4,17.6 1327.4,268.54 1306,289.94 1306,330 1323.4,347.4
+15V_2 on Top Layer "TOP_LAYER_+15V_2_P054" (solid, remove dead copper, pour order 54): 1124.11,505.59 1124.7,505 1480.39,505 1495,490.39 1495,380 1480,365 1131.46,365 1110,386.46 1110,491.48
-4V_2 on Top Layer "TOP_LAYER_-4V_2_P052" (solid, remove dead copper, pour order 52): 1058.5,355 1045,341.5 1045,304.53 1069.53,280 1212.76,280 1232.76,300 1232.76,337.24 1215,355
-4V_1 on Top Layer "TOP_LAYER_-4V_1_P040" (solid, remove dead copper, pour order 40): 625.72,234.7 640,248.98 640,551.5 653.5,565 702.82,565 715.16,577.34 715.16,622.75 715.16,654.81 690.93,665 636.69,665 622.33,652.81 622.33,604.01 598.98,570 485,570 460,545 460,252.7 476.88,234.7
+15V_1 on Top Layer "TOP_LAYER_+15V_1_P038" (solid, remove dead copper, pour order 38): 521.46,470 530,470 860,470 890,440 890,340 870,320 785,320 765,340 765,390 749,406 524,406 510,420 510,460 520,470 538.5,470
S_1 on Top Layer "TOP_LAYER_S_1_P036" (solid, remove dead copper, pour order 36): 720,310 690,280 690,160 670,140 597.55,140 575,117.45 575,0 760,0 800,40 800,190 850,240 850,310
AGND on Bottom Layer "BOTTOM_LAYER_AGND_P058" (solid, remove dead copper, pour order 58): 265,375 310,420 310,920 350,960 1430,960 1480,1010 1480,1280 1435,1325 60,1325 10,1275 10,410 45,375
S_2 on Bottom Layer "BOTTOM_LAYER_S_2_P050" (solid, remove dead copper, pour order 50): 1157.54,600 1390,600 1435,555 1435,7.4 1427.6,0 1335.28,0 1335.28,403.27 1308.54,430 1180,430 1170.22,439.78 1170.22,545 1165,545 1145,560 1145,586.21
+15V_1 on Bottom Layer "BOTTOM_LAYER_+15V_1_P048" (solid, remove dead copper, pour order 48): 694.21,530 715.16,550.95 715.16,622.75 722.41,630 740,630 750,620 750,500 650.24,400.24 569.76,400.24 560,410 560,454.83 595,485.89 595,510 622.33,530
S_1 on Bottom Layer "BOTTOM_LAYER_S_1_P046" (solid, remove dead copper, pour order 46): 580,671.5 524.99,671.5 504.83,651.33 504.83,494.83 490,480 490,410 501.46,398.54 530,398.54 540,408.54 540,480 551.3,491.3 581.3,491.3 590,500 590,661.5
no net on Bottom Layer "BOTTOM_LAYER_NONET_P044" (solid, remove dead copper, pour order 44): 580,655
-4V_1 on Bottom Layer "BOTTOM_LAYER_-4V_1_P042" (solid, remove dead copper, pour order 42): 690,680 620,680 610,670 610,555.79 614.49,551.3 681.3,551.3 692.99,562.99 692.99,677.01

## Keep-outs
Keep-Out Layer:
  text ".Layer_Name" at 577,-858.49 h60

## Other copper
Top Layer:
  text ".Layer_Name" at 577,-858.49 h60
Bottom Layer:
  text ".Layer_Name" at 577,-858.49 h60

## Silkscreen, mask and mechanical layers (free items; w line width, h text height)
Top Overlay:
  lines w10: 560,510 600,510
  text "HB Gate Driver Card01-UCC21530-Q1" at 205,1260 h30
  text "High Voltage" at 50.08,885 h30
  text "GND 5Vs EN" at 45,600 h30
  text "GND PWMB PWMA" at 20,540.02 h30
  text "S2" at 1425,155 h30
  text "G1" at 310,40 h30
  text "G2" at 1040,40 h30
  text "S1" at 740,35 h30
  text ".Layer_Name" at 577,-858.49 h60
Bottom Overlay:
  lines w10: 80,530 80,640
  text "'.PRJ_Number'.PCB_Rev" at 1435,1230 h80
  text "High Voltage" at 420,990 h30
  text "EN 5Vs GND" at 340,300 h30
  text "PWMA PWMB GND" at 405,240 h30
  text "G2" at 1180,175 h30
  text "S2" at 1485,175 h30
  text "S1" at 739.98,160 h30
  text "G1" at 405,155 h30
  text ".Layer_Name" at 577,-858.49 h60
Top Paste:
  text ".Layer_Name" at 577,-858.49 h60
Bottom Paste:
  text ".Layer_Name" at 577,-858.49 h60
Top Solder:
  text ".Layer_Name" at 577,-858.49 h60
  text ".Layer_Name" at 577,-858.49 h60
Bottom Solder:
  text ".Layer_Name" at 577,-858.49 h60
Drill Guide:
  text ".Layer_Name" at 577,-858.49 h60
M1 Board Outline:
  the board outline again, w7
  text ".Layer_Name" at 577,-858.49 h60
M2 Board Dimensions:
  rectangle: 0,-275 125,-150
  rectangle: 125,-400 500,-275
  lines w7: 0,-275 1000,-275 ; 125,-400 125,-150 ; 250,-400 250,-150 ; 500,-400 500,-150 ; 750,-400 750,-150 ; 0,-400 1000,-400 1000,-150 0,-150 0,-400
  text ".Layer_Name" at 577,-858.49 h60
M3 3D STEP Top:
  text ".Layer_Name" at 577,-858.49 h60
M4 3D STEP Bottom:
  text ".Layer_Name" at 577,-858.49 h60
M5 Assembly Top:
  lines w10: -292,-930.17 6308,-930.17 ; -292,-726.83 6310,-726.83 ; -292,-523.5 -292,-1133.5 3713,-1133.5 6310,-1133.5 6310,-523.5 -291.5,-523.5 -291.5,-1133.5 1284,-1133.5 ; 2173,-1133.5 2173,-523.5 ; 3440,-726.83 3440,-523.5 ; 4280,-726.83 4280,-523.5 ; 4902,-1140 4902,-937.17
  text "COMPONENTS MARKED 'DNP' SHOULD NOT BE POPULATED." at 1153.5,-318.5 h60
  text "ASSEMBLY VARIANT:" at 1153,-434 h60
  text ".VariantName" at 2189,-434 h60
  text "PCB VIEWED FROM TOP SIDE" at -228.5,-655.67 h60
  text "BOARD #:" at 2248,-655.67 h60
  text ".PRJ_Number" at 2793.5,-655.67 h60
  text "REV:" at 3638,-655.67 h60
  text ".PCB_Rev" at 3929.5,-655.67 h60
  text "SVN REV:" at 4476,-655.67 h60
  text ".VersionControl_RevNumber" at 4982,-655.67 h60
  text "TID #:" at 2248,-859 h60
  text ".TID" at 2793.5,-859 h60
  text "PLOT NAME =" at -228.5,-1064.34 h60
  text ".plot_File_Name" at 577,-1064.34 h60
  text "GENERATED    :" at 2250,-1064.34 h60
  text ".Print_Date" at 3119.5,-1064.34 h60
  text ".Print_Time" at 3848.5,-1064.34 h60
  text "TEXAS INSTRUMENTS" at 5113,-1064.34 h60
M6 Assembly Bottom:
  lines w10: -292.5,-727.33 6309.5,-727.33 ; -290.5,-930.67 6309.5,-930.67 ; 1115.5,-1140.5 1115.5,-937.67 ; 1737.5,-727.33 1737.5,-524 ; 2577.5,-727.33 2577.5,-524 ; 3844.5,-1134 3844.5,-524 ; 4733.5,-1134 6309,-1134 6309,-524 -292.5,-524 -292.5,-1134 2304.5,-1134 6309.5,-1134 6309.5,-524
  text "COMPONENTS MARKED 'DNP' SHOULD NOT BE POPULATED." at 6102,-318 h60
  text ".VariantName" at 5058,-434 h60
  text "ASSEMBLY VARIANT:" at 6097,-434 h60
  text ".VersionControl_RevNumber" at 1035.5,-656.17 h60
  text "SVN REV:" at 1541.5,-656.17 h60
  text ".PCB_Rev" at 2088,-656.17 h60
  text "REV:" at 2379.5,-656.17 h60
  text ".PRJ_Number" at 3224,-656.17 h60
  text "BOARD #:" at 3769.5,-656.17 h60
  text "PCB VIEWED FROM BOTTOM SIDE" at 6246,-656.17 h60
  text ".TID" at 3224,-859.5 h60
  text "TID #:" at 3769.5,-859.5 h60
  text "TEXAS INSTRUMENTS" at 904.5,-1064.84 h60
  text ".Print_Time" at 2169,-1064.84 h60
  text ".Print_Date" at 2898,-1064.84 h60
  text "GENERATED    :" at 3767.5,-1064.84 h60
  text ".plot_File_Name" at 5440.5,-1064.84 h60
  text "PLOT NAME =" at 6246,-1064.84 h60
M9 Title Sheet:
  drawing of 57 lines, arcs and shapes, not listed
  text "1" at 739.84,8036.5 h70
  text "2" at 3235.5,8036.5 h70
  text "3" at 5724.84,8036.5 h70
  text "4" at 8231.51,8036.5 h70
  text "5" at 10730.5,8036.5 h70
  text "6" at 13235.5,8036.5 h70
  text "A" at -416.5,6893.5 h70
  text "A" at 14383.5,6893.5 h70
  text "B" at -416.5,4513.5 h70
  text "B" at 14383.5,4513.5 h70
  text "C" at -416.5,2138.5 h70
  text "C" at 14383.5,2138.5 h70
  text "PROJECT TITLE:" at 11343.5,277.5 h45
  text ".PRJ_Title" at 11393.5,144.17 h70
  text "DESIGNED FOR:" at 11343.5,-23.5 h45
  text ".PRJ_Customer" at 11393.5,-163.5 h70
  text "D" at -416.5,-231.5 h70
  text "D" at 14383.5,-231.5 h70
  text "FILE NAME:" at 11343.5,-323.5 h45
  text ".PCB_File_Name_No_Path" at 11393.5,-443.5 h70
  text "Texas Instruments (TI) and/or its licensors do not warrant the accuracy or completeness of this specification" at 6374,-605.34 h45
  text "ENGINEER:" at 11343.5,-613.5 h45
  text "LAYOUT BY:" at 12848.5,-613.5 h45
  text "or any information contained therein. TI and/or its licensors do not warrant that this design will meet" at 6329.01,-718 h45
  text ".PRJ_Engineer" at 11393.5,-768.49 h70
  text ".PCB_Layout" at 12899,-768.49 h70
  text "the specifications, will be suitable for your application or fit for any particular purpose, or will operate in" at 6329.01,-830.67 h45
  text ".Layer_Name" at 577,-858.49 h60
  text "ALTIUM DESIGNER VERSION:" at 12848.5,-923.5 h45
  text "an implementation. TI and/or its licensors do not warrant that the design is production worthy. You should" at 6329.01,-943.33 h45
  text "completely validate and test your design implementation to confirm the system functionality for your application." at 6374,-1056 h45
  text ".print_Scale" at 11393.5,-1056.83 h70
  text ".Application_BuildNumber" at 12899,-1056.83 h70
  text "1" at 739.84,-1263.5 h70
  text "2" at 3235.5,-1263.5 h70
  text "3" at 5724.84,-1263.5 h70
  text "4" at 8231.51,-1263.5 h70
  text "5" at 10730.5,-1263.5 h70
  text "6" at 13235.5,-1263.5 h70
M10 Fab Notes:
  drawing of 189 lines, arcs and shapes, not listed
  text "DESIGN INFORMATION" at 12382.02,6356.17 h60
  text "MIN. TRACK WIDTH:" at 11737.46,6224.05 h60
  text "8" at 12833.7,6224.05 h60
  text "MIL" at 12988.46,6224.05 h60
  text "MIN. CLEARANCE:" at 11737.46,6099.92 h60
  text "0.2" at 12773.7,6099.93 h60
  text "mm" at 12988.46,6099.92 h60
  text "MIN. VIA PAD SIZE:" at 11737.46,5975.8 h60
  text "24" at 12803.71,5975.8 h60
  text "MIL" at 12988.46,5975.8 h60
  text "0.05mm (2MIL)" at 12432.46,5845.9 h60
  text "MINIMUM ANNULAR RING" at 11408.23,5837.67 h60
  text "EXTERNAL" at 13140.46,5837.67 h60
  text "PER" at 11608.23,5727.55 h60
  text "IPC-D-275 CLASS 2 LEVEL C" at 11828.23,5727.54 h60
  text "MIL, HOLES" at 13316.46,5627.07 h60
  text "+/-" at 12924,5618.48 h60
  text "+/-" at 13778,5618.48 h60
  text "REGISTRATION TOLERANCES:" at 11408.23,5617.42 h60
  text "METAL" at 12608,5617.42 h60
  text "5" at 13184.2,5617.42 h60
  text "3" at 14017.2,5617.42 h60
  text "MIL" at 14133.46,5617.42 h60
  text "HOLE SIZE TOLERANCE (UNLESS OTHERWISE SPECIFIED):" at 11408.23,5519.1 h60
  text "+/-" at 13778,5516.23 h60
  text "3" at 14017.2,5515.17 h60
  text "MIL" at 14133.46,5515.17 h60
  text "MATERIAL:" at 11333.46,5377.52 h60
  text "FR-4 High Tg" at 12319.9,5249 h60
  text "X" at 12175.46,5241.01 h60
  text "FR-408" at 11754.46,5236.49 h60
  text "OTHER" at 13242.46,5236.49 h60
  text "62 MIL (1.6mm) +/-10%" at 12074.56,5093.46 h60
  text "X" at 11954.46,5091.01 h60
  text "THICKNESS:" at 11408.23,5085.24 h60
  text "OTHER" at 13359.46,5085.24 h60
  text "TOLERANCE:" at 11408.23,4946.92 h60
  text "X" at 12256.46,4946.92 h60
  text "ANSI IPC-6012 TYPE 3 CLASS 2" at 12434.48,4946.92 h60
  text "OTHER +/-" at 12434.46,4802.73 h60
  text "BOW & TWIST:" at 11408.23,4657.54 h60
  text "X" at 12256.46,4657.54 h60
  text "ANSI IPC-6012 TYPE 3 CLASS 2" at 12434.48,4657.54 h60
  text "OTHER +/-" at 12434.46,4510.85 h60
  text "DRILLING:" at 11333.46,4380.23 h60
  text "NC_DRILL FILES" at 13094.46,4275.04 h60
  text "REFERENCE:" at 11408.23,4271.1 h60
  text "X" at 12065.46,4271.01 h60
  text "AS SHOWN" at 12243.46,4271.1 h60
  text "X" at 12966.46,4271.1 h60
  text "OTHER" at 13392.46,4128.85 h60
  text "PTH COPPER THICKNESS:" at 11407.91,4125.32 h60
  text "X" at 12547.14,4125.32 h60
  text "20-30 um" at 12675.14,4125.32 h60
  text "BOARD FINISH:" at 11333.46,3977.73 h60
  text "SILKSCREEN:" at 11488.68,3867.6 h60
  text "X" at 12446.46,3867.6 h60
  text "TOP" at 12563.46,3867.6 h60
  text "X" at 12956.46,3867.6 h60
  text "BOTTOM" at 13074.46,3867.6 h60
  text "SILKSCREEN COLOR:" at 11488.68,3712.41 h60
  text "X" at 12445.46,3712.41 h60
  text "WHITE" at 12563.46,3712.41 h60
  text "OTHER" at 13074.46,3712.41 h60
  text "X" at 12576.46,3568.96 h60
  text "GREEN" at 12694.46,3568.96 h60
  text "OTHER" at 13312.46,3568.96 h60
  text "SOLDER RESIST COLOR:" at 11488.68,3562.1 h60
  text "X" at 12576.46,3414.71 h60
  text "MATTE" at 12694.46,3414.71 h60
  text "SEMI-GLOSS" at 13312,3414.07 h60
  text "IMMERSION GOLD (ENIG)" at 12394.46,3241.94 h60
  text "ENEPIG" at 13732,3234.72 h60
  text "SURFACE FINISH:" at 11333.46,3233.72 h60
  text "X" at 12216.46,3233.72 h60
  text "IMM. TIN/SILVER OR EQUIV" at 11663,3096.4 h60
  text "OTHER" at 13094.46,3092.47 h60
  text "ARRAY/PANEL:" at 11333.46,2937.09 h60
  text "CUT AND TRIM PER M1 BOARD OUTLINE" at 12394.46,2928.87 h60
  text "N.C. ROUTE" at 12394.46,2792.9 h60
  text "X" at 13082.46,2792.9 h60
  text "V. SCORE" at 13260.46,2792.9 h60
  text "CERTIFICATION:" at 11333.46,2663.77 h60
  text "MATERIALS AND WORKMANSHIP FOR ALL PCBS" at 12058.46,2663.77 h60
  text "TO MEET OR EXCEED THE REQUIREMENTS OF:" at 12058.46,2569.71 h60
  text "X" at 11695.97,2441.08 h60
  text "ANSI IPC-A-600F CLASS ->" at 11823.96,2441.08 h60
  text "X" at 13471.97,2441.08 h60
  text "2" at 13581.96,2441.08 h60
  text "1" at 13266.96,2439.58 h60
  text "3" at 13935.96,2439.58 h60
  text "X" at 12507.97,2293.39 h60
  text "RoHS" at 12635.96,2293.39 h60
  text "OTHER" at 13280.36,2293.39 h60
  text "PER ORDER" at 13677.42,2293.39 h60
  text "ALL BOARDS MUST MEET OR EXCEED UL94-V0 REQUIREMENTS." at 11361,2139.57 h60
  text "PCB MUST BEAR THE UL94V-0 UL REGISTERED MATERIAL ID NUMBER" at 11361,2023.5 h60
  text "ADDITIONAL REQUIREMENTS:" at 11333.46,1854.08 h60
  text "MICROSECTION:" at 11408.23,1746.95 h60
  text "YES" at 12313.96,1746.95 h60
  text "REQUIRED" at 13175.46,1602.62 h60
  text "BARE BOARD ELEC. TEST:" at 11408.23,1599.76 h60
  text "NONE" at 12713.96,1599.76 h60
  text "X" at 13057.46,1599.76 h60
  text "PER ORDER" at 13767.46,1599.76 h60
  text "XX MIL VIAS REQUIRE NON-CONDUCTIVE FILL AND PLANARIZE" at 11576.38,1394.82 h59
  text "XX MIL VIAS REQUIRE CONDUCTIVE FILL AND PLANARIZE" at 11584.38,1290.84 h60
  text "OUTER XX MIL TRACES REQUIRE 50 OHM SINGLE-ENDED IMPEDANCE" at 11583.39,1127.46 h58
  text "LAYER 2 & 3 (INNER LAYERS) XX MIL WIDE, XX MIL SPACE / TRACES REQUIRE 100 OHM DIFFERENTIAL IMPEDANCE" at 11575.39,891.74 h60
  text ".Layer_Name" at 577,-858.49 h60
M11 Gerber Information:
  lines w10: -292,-930.17 6308,-930.17 ; -292,-726.83 6310,-726.83 ; -292,-523.5 -292,-1133.5 3713,-1133.5 6310,-1133.5 6310,-523.5 -291.5,-523.5 -291.5,-1133.5 1284,-1133.5 ; 2173,-1133.5 2173,-523.5 ; 3440,-726.83 3440,-523.5 ; 4280,-726.83 4280,-523.5 ; 4902,-1140 4902,-937.17
  text "ALL ARTWORK VIEWED FROM TOP SIDE" at -228.5,-655.67 h60
  text "BOARD #:" at 2248,-655.67 h60
  text ".PRJ_Number" at 2793.5,-655.67 h60
  text "REV:" at 3638,-655.67 h60
  text ".PCB_Rev" at 3929.5,-655.67 h60
  text "SVN REV:" at 4476,-655.67 h60
  text ".VersionControl_RevNumber" at 4982,-655.67 h60
  text "LAYER NAME =" at -228.5,-858.49 h60
  text "TID #:" at 2248,-859 h60
  text ".TID" at 2793.5,-859 h60
  text "PLOT NAME =" at -228.5,-1064.34 h60
  text ".plot_File_Name" at 577,-1064.34 h60
  text "GENERATED    :" at 2250,-1064.34 h60
  text ".Print_Date" at 3119.5,-1064.34 h60
  text ".Print_Time" at 3848.5,-1064.34 h60
  text "TEXAS INSTRUMENTS" at 5113,-1064.34 h60
M12 Stackup:
  drawing of 191 lines, arcs and shapes, not listed
  text "Layer" at 9797.84,7492.5 h60
  text "Name" at 10207.76,7492.5 h60
  text "Material" at 11137.5,7492.5 h60
  text "Thickness" at 11997.27,7492.5 h60
  text "Constant" at 12647.1,7492.5 h60
  text "Board Layer Stack" at 13216.96,7492.5 h60
  text "1" at 9797.84,7372.5 h60
  text "Top Overlay" at 10207.76,7372.5 h60
  text "2" at 9797.84,7252.5 h60
  text "Top Solder" at 10207.76,7252.5 h60
  text "Solder Resist" at 11137.5,7252.5 h60
  text "0.40mil" at 11997.27,7252.5 h60
  text "3.5" at 12647.1,7252.5 h60
  text "3" at 9797.84,7132.5 h60
  text "Top Layer" at 10207.76,7132.5 h60
  text "Copper" at 11137.5,7132.5 h60
  text "1.40mil" at 11997.27,7132.5 h60
  text "4" at 9797.84,7012.5 h60
  text "Dielectric2" at 10207.76,7012.5 h60
  text "FR-4" at 11137.5,7012.5 h60
  text "59.20mil" at 11997.27,7012.5 h60
  text "4.8" at 12647.1,7012.5 h60
  text "5" at 9797.84,6892.5 h60
  text "Bottom Layer" at 10207.76,6892.5 h60
  text "Copper" at 11137.5,6892.5 h60
  text "1.40mil" at 11997.27,6892.5 h60
  text "6" at 9797.84,6772.5 h60
  text "Bottom Solder" at 10207.76,6772.5 h60
  text "Solder Resist" at 11137.5,6772.5 h60
  text "0.40mil" at 11997.27,6772.5 h60
  text "3.5" at 12647.1,6772.5 h60
  text "7" at 9797.84,6652.5 h60
  text "Bottom Overlay" at 10207.76,6652.5 h60
  text ".Layer_Name" at 577,-858.49 h60
M13 Component Bodies Top:
  text ".Layer_Name" at 577,-858.49 h60
M14 Component Bodies Bottom:
  text ".Layer_Name" at 577,-858.49 h60
M15 Courtyards Top:
  text ".Layer_Name" at 577,-858.49 h60
M16 Courtyards Bottom:
  text ".Layer_Name" at 577,-858.49 h60
Drill Drawing:
  circle w10: c-1041.28,-1680.28 r27.63
  lines w10: -1068.91,-1901.29 -1013.66,-1901.29 -1041.28,-1956.55 -1068.91,-1901.29 ; -1068.91,-1832.23 -1013.66,-1832.23 -1013.66,-1776.97 -1068.91,-1776.97 -1068.91,-1832.23
  lines w12: -1119,-1993.84 2112.49,-1993.84 ; -1119,-1620.88 2112.49,-1620.88 ; -781.14,-2118.16 -781.14,-1496.56 ; -449.14,-2118.16 -449.14,-1496.56 ; 187.43,-2118.16 187.43,-1496.56 ; 446.57,-2118.16 446.57,-1496.56 ; 821.72,-2118.16 821.72,-1496.56 ; 1546.05,-2118.16 1546.05,-1496.56 ; -1119,-2118.16 2112.49,-2118.16 2112.49,-1496.56 -1119,-1496.56 -1119,-2118.16
  text ".Layer_Name" at 577,-858.49 h60
  text "Symbol" at -1044.41,-1583.59 h72
  text "Quantity" at -743.84,-1583.59 h72
  text "Finished Hole Size" at -411.84,-1583.59 h72
  text "Plated" at 224.72,-1583.59 h72
  text "Hole Type" at 483.86,-1583.59 h72
  text "Drill Layer Pair" at 859.02,-1583.59 h72
  text "Hole Tolerance" at 1583.35,-1583.59 h72
  text "30" at -743.84,-1707.91 h60
  text "10.00mil (0.254mm)" at -411.84,-1707.91 h60
  text "PTH" at 224.72,-1707.91 h60
  text "Round" at 483.86,-1707.91 h60
  text "Top Layer - Bottom Layer" at 859.02,-1707.91 h60
  text "6" at -743.84,-1832.23 h60
  text "39.37mil (1.000mm)" at -411.84,-1832.23 h60
  text "PTH" at 224.72,-1832.23 h60
  text "Round" at 483.86,-1832.23 h60
  text "Top Layer - Bottom Layer" at 859.02,-1832.23 h60
  text "4" at -743.84,-1956.55 h60
  text "64.96mil (1.650mm)" at -411.84,-1956.55 h60
  text "PTH" at 224.72,-1956.55 h60
  text "Round" at 483.86,-1956.55 h60
  text "Top Layer - Bottom Layer" at 859.02,-1956.55 h60
  text "40 Total" at -743.84,-2080.87 h60
M17 Embedded Cavity:
  text ".Layer_Name" at 577,-858.49 h60
M18 Embedded Assembly:
  text ".Layer_Name" at 577,-858.49 h60
M19 Embedded Keepout:
  text ".Layer_Name" at 577,-858.49 h60

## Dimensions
0,-400 to 1000,-400 on M2 Board Dimensions
0,0 to 0,1330 on M2 Board Dimensions
0,0 to 1550,0 on M2 Board Dimensions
